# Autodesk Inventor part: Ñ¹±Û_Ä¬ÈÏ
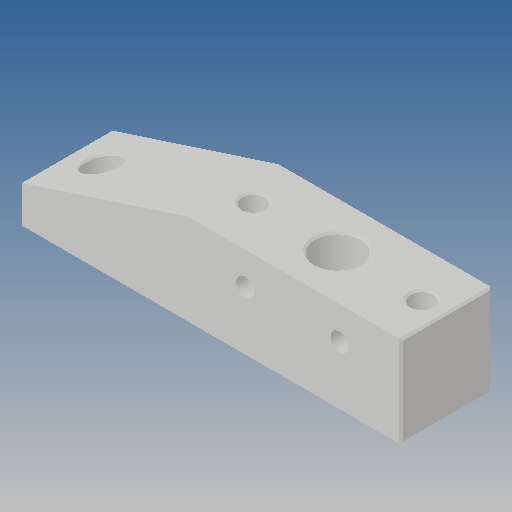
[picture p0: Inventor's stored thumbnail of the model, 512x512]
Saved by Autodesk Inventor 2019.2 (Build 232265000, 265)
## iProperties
Created: 2012-03
Part Number: Ñ¹±Û_Ä¬ÈÏ
Material: Ogólny
Document SubType Name: Modeling
Designer: CADENGINEERING4
Density: 1 g/cm^3
Appearance: Domyślna
Author: CADENGINEERING4
Revision Number: ÈÎºÎ
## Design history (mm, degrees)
feature "NONE"
node "Bryła1"
